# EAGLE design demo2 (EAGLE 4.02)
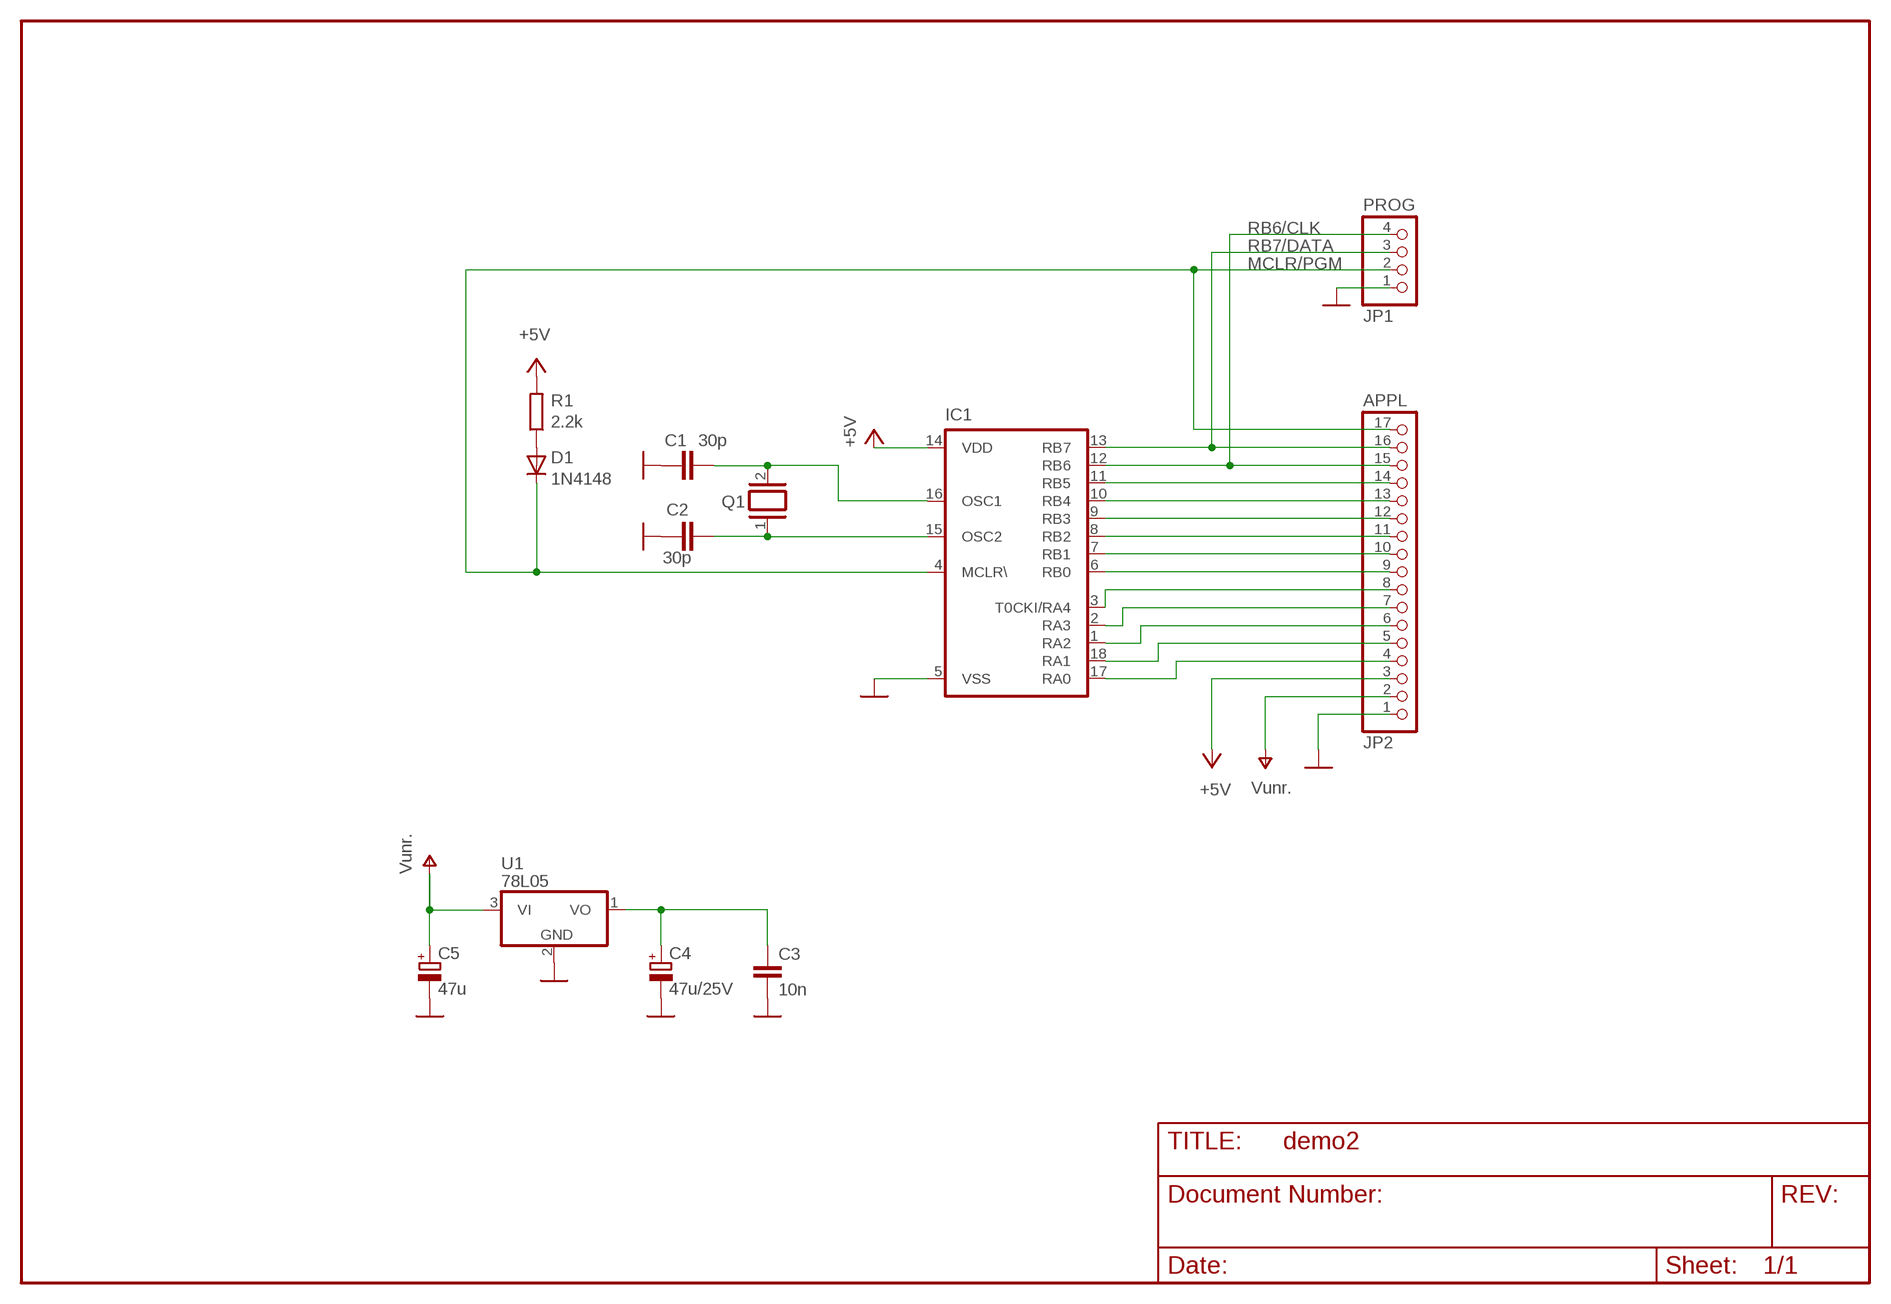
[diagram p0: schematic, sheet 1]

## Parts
C1  30p  C-EUC1206  [C1206]
C2  30p  C-EUC1206  [C1206]
C3  10n  C-EU025-025X050  [C025-025X050]
C4  47u/25V  CPOL-TAP5-45  [TAP5-45]
C5  47u  CPOL-TAP5-45  [TAP5-45]
D1  1N4148  [DO35-10]
IC1  PIC16F84AP  [DIL18]
JP1  PROG  PINHD-1X4  [1X04]
JP2  APPL  PINHD-1X17  [1X17]
Q1  XTAL/S  [QS]
R1  2.2k  R-EU_R1206  [R1206]
U1  78L05  78LXXZ  [TO92]

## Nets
GND [power]: C1.2 C2.2 C3.1 C4.- C5.- IC1.5(VSS) JP1.1 JP2.1 U1.2(GND)
MCLR/PGM: D1.K IC1.4(MCLR\) JP1.2 JP2.17
N$1: C3.2 C4.+ U1.1(VO)
N$2: C1.1 IC1.16(OSC1) Q1.2
N$3: C2.1 IC1.15(OSC2) Q1.1
N$5: D1.A R1.1
RA0: IC1.17(RA0) JP2.4
RA1: IC1.18(RA1) JP2.5
RA2: IC1.1(RA2) JP2.6
RA3: IC1.2(RA3) JP2.7
RA4: IC1.3(T0CKI/RA4) JP2.8
RB0: IC1.6(RB0) JP2.9
RB1: IC1.7(RB1) JP2.10
RB2: IC1.8(RB2) JP2.11
RB3: IC1.9(RB3) JP2.12
RB4: IC1.10(RB4) JP2.13
RB5: IC1.11(RB5) JP2.14
RB6/CLK: IC1.12(RB6) JP1.4 JP2.15
RB7/DATA: IC1.13(RB7) JP1.3 JP2.16
V+ [power]: C5.+ JP2.2 U1.3(VI) ; supply symbol labelled Vunr.
VCC [power]: IC1.14(VDD) JP2.3 R1.2 ; supply symbol labelled +5V

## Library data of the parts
C1-C3 = rcl:C-EU: capacitor EUrop Symbol
C4 C5 = rcl:CPOL-: polarity capacitor (Tantalum, Electrolyt) EUrop Symbol
D1 = diode:1N4148: 1N4148 - High Conductance Fast Diode
IC1 = microchip:PIC16F8*: 8-Bit Microcontroller PIC16F8X Family - CMOS Flash/EEPROM Pin Compatible : PIC16F83, PIC16CR83, PIC16F84A, PIC16CR84 see also PIC16C*
JP1 = PINHEAD:PINHD-1X4
JP2 = PINHEAD:PINHD-1X17
Q1 = special:XTAL/S
R1 = rcl:R-EU_: resistor EUrop Symbol
U1 = linear:78LXXZ: positiv voltage regulator / low power TO92

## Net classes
0 default: width 0.2 mm, drill 0.2 mm, clearance 0.8 mm
1 power: width 0.4 mm, drill 0.2 mm, clearance 0.2 mm

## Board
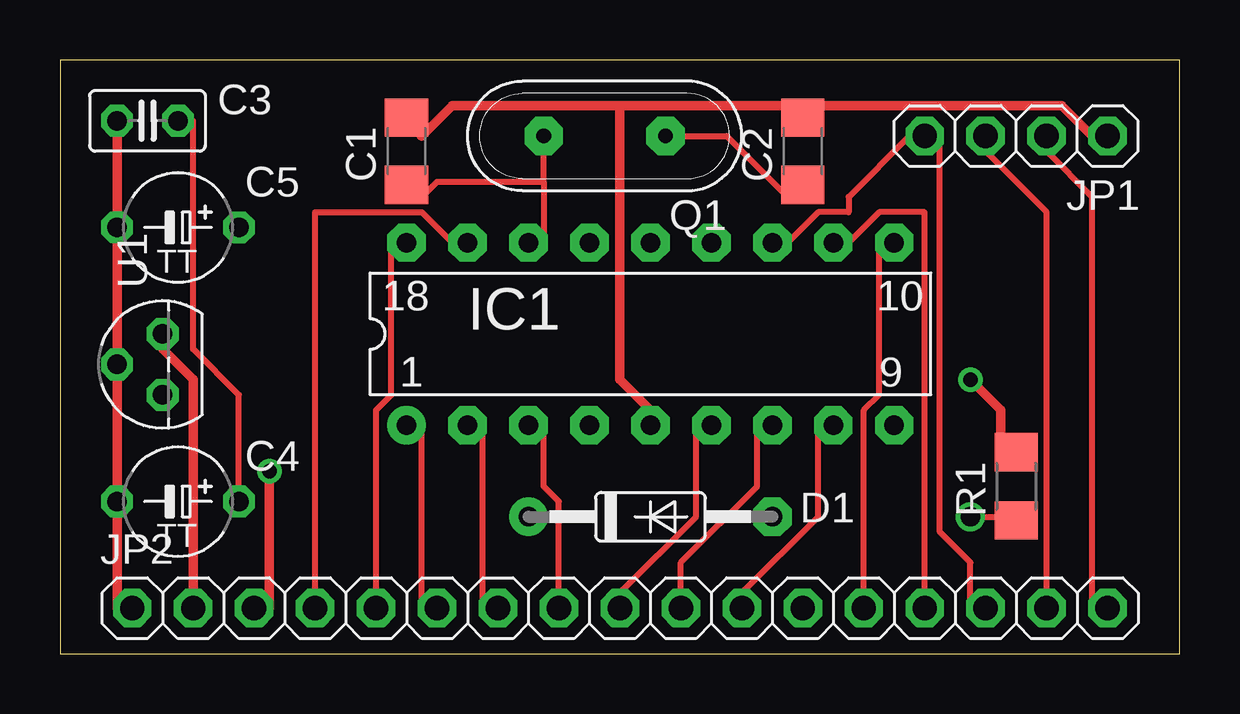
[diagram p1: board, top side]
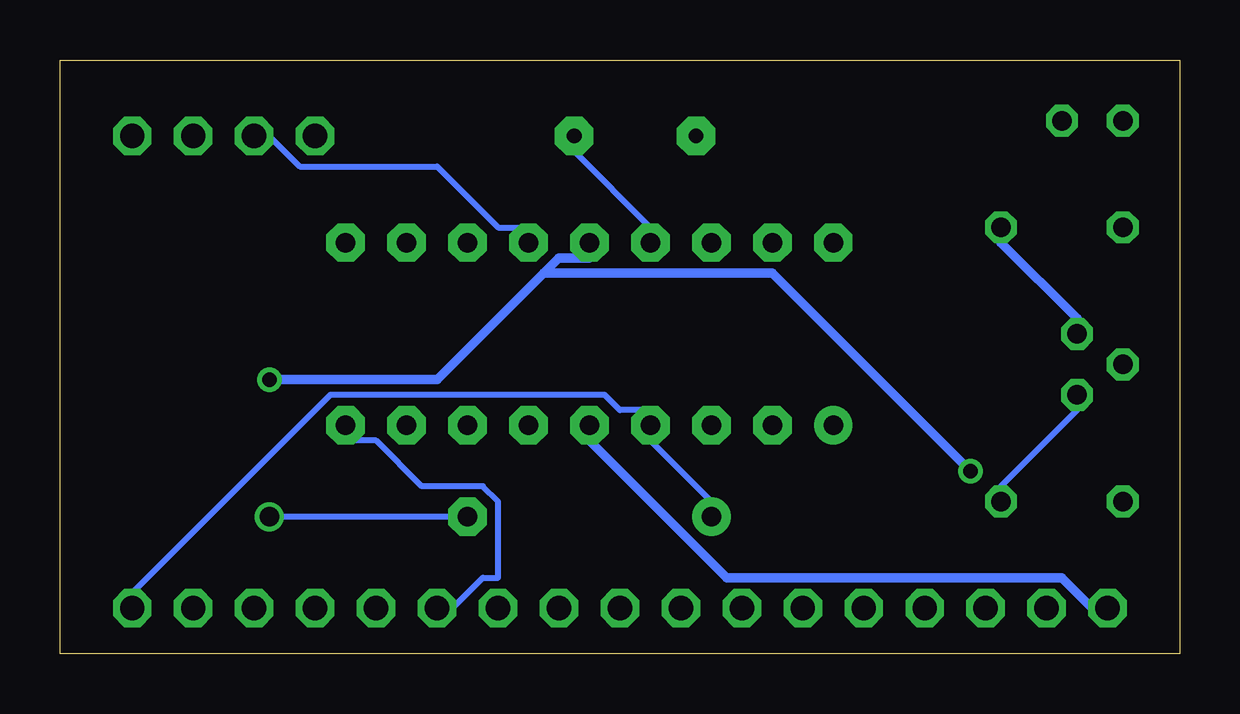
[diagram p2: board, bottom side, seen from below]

Size 46.66 x 24.75 mm. Coordinates in mm from the lower left corner, seen from the top.
Outline: 0,0 46.66,0 46.66,24.75 0,24.75 0,0
Copper layers used: Top, Bottom

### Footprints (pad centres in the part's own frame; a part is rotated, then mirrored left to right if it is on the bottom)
C1206 = smd 1.6 x 1.8: 1 -1.4,0; 2 1.4,0
C025-025X050 = drill 0.813 octagon: 1 -1.27,0; 2 1.27,0
TAP5-45 = drill 0.813 octagon: + 2.54,0; - -2.54,0
DO35-10 = drill 0.813 pad 1.6 octagon: A 5.08,0 | drill 0.813 pad 1.6 round: K -5.08,0
DIL18 = drill 0.813 pad 1.6 round: 1 -10.16,-3.81 | drill 0.813 pad 1.6 octagon: 2 -7.62,-3.81; 3 -5.08,-3.81; 4 -2.54,-3.81; 5 0,-3.81; 6 2.54,-3.81; 7 5.08,-3.81; 8 7.62,-3.81; 9 10.16,-3.81; 10 10.16,3.81; 11 7.62,3.81; 12 5.08,3.81; 13 2.54,3.81; 14 0,3.81; 15 -2.54,3.81; 16 -5.08,3.81; 17 -7.62,3.81; 18 -10.16,3.81
1X04 = drill 1.016 pad 1.6 octagon: 1 -3.81,0; 2 -1.27,0; 3 1.27,0; 4 3.81,0
1X17 = drill 1.016 pad 1.6 octagon: 1 -20.32,0; 2 -17.78,0; 3 -15.24,0; 4 -12.7,0; 5 -10.16,0; 6 -7.62,0; 7 -5.08,0; 8 -2.54,0; 9 0,0; 10 2.54,0; 11 5.08,0; 12 7.62,0; 13 10.16,0; 14 12.7,0; 15 15.24,0; 16 17.78,0; 17 20.32,0
QS = drill 0.61 pad 1.6 octagon: 1 -2.54,0; 2 2.54,0
R1206 = smd 1.6 x 1.803: 1 -1.422,0; 2 1.422,0
TO92 = drill 0.813 octagon: 1 -1.27,0; 2 0,1.905; 3 1.27,0

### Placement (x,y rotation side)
C1  14.44,20.95 90 top
C2  30.95,20.95 90 top
C3  3.65,22.22 0 top
C4  4.92,6.34 0 top
C5  4.92,17.77 0 top
D1  24.6,5.71 0 top
IC1  24.6,13.33 0 top
JP1  39.84,21.58 180 top
JP2  23.33,1.9 0 top
Q1  22.69,21.58 180 top
R1  39.84,6.98 90 top
U1  4.28,12.06 90 top

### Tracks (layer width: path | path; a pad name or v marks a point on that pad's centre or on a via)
GND
  Top 0.4: JP1.1 43.02,21.58 41.75,22.86 31.58,22.86 C2.2 30.31,22.86 23.33,22.86 | 23.33,22.86 16.34,22.86 15.08,21.58 C1.2 | C3.1 C5.- U1.2 C4.- 2.38,1.9 JP2.1 | 23.33,22.86 23.33,11.43 24.6,10.16 IC1.5
  Bottom 0.4: IC1.5 24.6,8.89 18.88,3.17 4.92,3.17 3.65,1.9 JP2.1
MCLR/PGM
  Top 0.254: JP2.17 43.02,1.9 43.02,19.04 41.11,20.95 JP1.2
  Bottom 0.254: D1.K 19.52,6.34 22.06,8.89 IC1.4 22.06,10.16 23.33,10.16 23.96,10.79 35.4,10.79 43.65,2.54 JP2.17
N$1
  Top 0.254: C3.2 5.55,22.22 5.55,12.7 7.46,10.79 C4.+
  Bottom 0.254: C4.+ 7.46,6.98 4.28,10.16 U1.1
N$2
  Top 0.254: 20.15,19.68 20.15,17.14 IC1.16 | 20.15,19.68 Q1.2 | 20.15,19.68 15.71,19.68 15.08,19.04 C1.1
N$3
  Top 0.254: C2.1 30.31,19.04 27.77,21.58 Q1.1
  Bottom 0.254: IC1.15 22.06,17.77 25.23,20.95 Q1.1
N$5  (via drill 0.8)
  Top 0.254: v37.94,5.71 39.21,5.71 R1.1
  Bottom 0.254: D1.A v37.94,5.71
RA0
  Top 0.254: IC1.17 16.34,17.14 15.08,18.41 10.63,18.41 JP2.4
RA1
  Top 0.254: IC1.18 13.8,17.14 13.8,10.79 13.17,10.16 JP2.5
RA2
  Top 0.254: IC1.1 15.08,9.52 15.08,1.9 JP2.6
RA3
  Top 0.254: IC1.2 17.61,9.52 17.61,1.9 JP2.7
RA4
  Top 0.254: IC1.3 20.15,9.52 20.15,6.98 20.79,6.34 JP2.8
RB0
  Top 0.254: IC1.6 26.5,9.52 26.5,5.71 23.33,2.54 JP2.9
RB1
  Top 0.254: IC1.7 29.04,9.52 29.04,6.98 25.87,3.8 JP2.10
RB2
  Top 0.254: IC1.8 31.58,9.52 31.58,5.71 28.41,2.54 JP2.11
RB3
  Bottom 0.254: IC1.9 34.76,8.89 33.49,8.89 31.58,6.98 29.04,6.98 28.41,6.34 28.41,3.17 29.04,3.17 30.31,1.9 JP2.12
RB4
  Top 0.254: IC1.10 34.12,17.14 34.12,10.79 33.49,10.16 JP2.13
RB5
  Top 0.254: IC1.11 32.85,17.14 34.12,18.41 36.03,18.41 JP2.14
RB6/CLK
  Top 0.254: IC1.12 30.31,17.14 31.58,18.41 32.85,18.41 32.85,19.04 35.4,21.58 JP1.4 36.66,21.58 36.66,5.08 37.94,3.8 37.94,1.9 JP2.15
RB7/DATA
  Top 0.254: JP2.16 41.11,18.41 38.57,20.95 JP1.3
  Bottom 0.254: IC1.13 27.14,17.77 28.41,17.77 30.95,20.31 36.66,20.31 37.94,21.58 JP1.3
V+
  Top 0.4: JP2.2 5.55,11.43 4.28,12.7 U1.3
  Bottom 0.4: U1.3 4.28,13.97 7.46,17.14 C5.+
VCC  (via drill 0.61)
  Top 0.4: v37.94,11.43 39.21,10.16 39.21,8.89 R1.2 | v8.72,7.62 8.72,1.9 JP2.3
  Bottom 0.4: 26.5,15.87 30.95,11.43 v37.94,11.43 | 26.5,15.87 25.87,16.5 24.6,16.5 IC1.14 | v8.72,7.62 16.98,15.87 26.5,15.87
